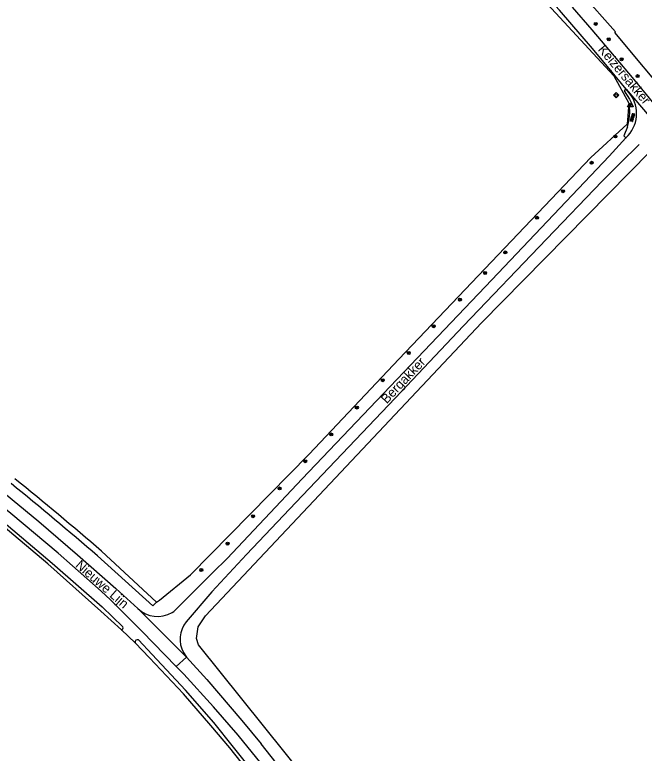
# Model space of a CAD drawing. Extents: x 124000 to 129000, y 395500 to 397503.
# Drawn here: x 126314 to 126479.9, y 396772.3 to 396968.6 of the extents above; entities that cross this region are included whole.
import ezdxf

# ---------------------------------------------------------------- set-up
doc = ezdxf.new("R2010")
doc.units = 0
for name, color, linetype in [('gg-afsc-erfafscheiding', 7, 'Continuous'), ('gg-anno-openbare ruimte label', 7, 'Continuous'), ('gg-knt-bronhoudergrens', 7, 'Continuous'), ('gg-knt-verharding', 7, 'Continuous'), ('gg-kntw-bovenkant insteek waterloop', 7, 'Continuous'), ('gt-grn-groengrens', 7, 'Continuous'), ('gt-grn-vlakafsluiter', 7, 'Continuous'), ('gt-grn-weggrens', 7, 'Continuous'), ('gt-symb-boom', 7, 'Continuous'), ('gt-symb-overige verharding', 7, 'Continuous'), ('gt-symb-rioolschacht', 7, 'Continuous'), ('gt-symb-waterafsluiter', 7, 'Continuous'), ('gx-grn-maaiveld', 7, 'Continuous')]:
    doc.layers.add(name, color=color, linetype=linetype)

# ---------------------------------------------------------------- blocks, each defined once
blk = doc.blocks.new('gt0-BOOM')
at = {"layer": 'gt-symb-boom'}
for radius in [0.4, 0.2]:
    blk.add_circle((0, 0), radius, dxfattribs=at)
blk = doc.blocks.new('gt0-OVH')
at = {"layer": 'gt-symb-overige verharding'}
for points in [[(-0.97, 0.3), (-0.97, 0.31), (-0.96, 0.32), (-0.97, 0.33), (-0.97, 0.34), (-0.98, 0.35), (-0.99, 0.35), (-1, 0.36), (-1.01, 0.35), (-1.02, 0.35), (-1.03, 0.34), (-1.03, 0.33), (-1.04, 0.32), (-1.03, 0.31), (-1.03, 0.3), (-1.02, 0.29), (-1.01, 0.29), (-1, 0.28), (-0.99, 0.29), (-0.98, 0.29)], [(-0.87, 0.11), (-0.87, 0.12), (-0.86, 0.13), (-0.87, 0.14), (-0.87, 0.15), (-0.88, 0.16), (-0.89, 0.16), (-0.9, 0.16), (-0.91, 0.16), (-0.92, 0.16), (-0.93, 0.15), (-0.93, 0.14), (-0.94, 0.13), (-0.93, 0.12), (-0.93, 0.11), (-0.92, 0.1), (-0.91, 0.09), (-0.9, 0.09), (-0.89, 0.09), (-0.88, 0.1)], [(-0.77, 0.3), (-0.77, 0.31), (-0.76, 0.32), (-0.77, 0.33), (-0.77, 0.34), (-0.78, 0.35), (-0.79, 0.35), (-0.8, 0.36), (-0.81, 0.35), (-0.82, 0.35), (-0.83, 0.34), (-0.83, 0.33), (-0.84, 0.32), (-0.83, 0.31), (-0.83, 0.3), (-0.82, 0.29), (-0.81, 0.29), (-0.8, 0.28), (-0.79, 0.29), (-0.78, 0.29)], [(-0.67, 0.11), (-0.67, 0.12), (-0.66, 0.13), (-0.67, 0.14), (-0.67, 0.15), (-0.68, 0.16), (-0.69, 0.16), (-0.7, 0.16), (-0.71, 0.16), (-0.72, 0.16), (-0.73, 0.15), (-0.73, 0.14), (-0.74, 0.13), (-0.73, 0.12), (-0.73, 0.11), (-0.72, 0.1), (-0.71, 0.09), (-0.7, 0.09), (-0.69, 0.09), (-0.68, 0.1)], [(-0.57, 0.3), (-0.57, 0.31), (-0.56, 0.32), (-0.57, 0.33), (-0.57, 0.34), (-0.58, 0.35), (-0.59, 0.35), (-0.6, 0.36), (-0.61, 0.35), (-0.62, 0.35), (-0.63, 0.34), (-0.63, 0.33), (-0.64, 0.32), (-0.63, 0.31), (-0.63, 0.3), (-0.62, 0.29), (-0.61, 0.29), (-0.6, 0.28), (-0.59, 0.29), (-0.58, 0.29)], [(-0.47, 0.11), (-0.47, 0.12), (-0.46, 0.13), (-0.47, 0.14), (-0.47, 0.15), (-0.48, 0.16), (-0.49, 0.16), (-0.5, 0.16), (-0.51, 0.16), (-0.52, 0.16), (-0.53, 0.15), (-0.53, 0.14), (-0.54, 0.13), (-0.53, 0.12), (-0.53, 0.11), (-0.52, 0.1), (-0.51, 0.09), (-0.5, 0.09), (-0.49, 0.09), (-0.48, 0.1)], [(-0.37, 0.3), (-0.37, 0.31), (-0.36, 0.32), (-0.37, 0.33), (-0.37, 0.34), (-0.38, 0.35), (-0.39, 0.35), (-0.4, 0.36), (-0.41, 0.35), (-0.42, 0.35), (-0.43, 0.34), (-0.43, 0.33), (-0.44, 0.32), (-0.43, 0.31), (-0.43, 0.3), (-0.42, 0.29), (-0.41, 0.29), (-0.4, 0.28), (-0.39, 0.29), (-0.38, 0.29)], [(-0.27, 0.11), (-0.27, 0.12), (-0.26, 0.13), (-0.27, 0.14), (-0.27, 0.15), (-0.28, 0.16), (-0.29, 0.16), (-0.3, 0.16), (-0.31, 0.16), (-0.32, 0.16), (-0.33, 0.15), (-0.33, 0.14), (-0.34, 0.13), (-0.33, 0.12), (-0.33, 0.11), (-0.32, 0.1), (-0.31, 0.09), (-0.3, 0.09), (-0.29, 0.09), (-0.28, 0.1)], [(-0.17, 0.3), (-0.17, 0.31), (-0.16, 0.32), (-0.17, 0.33), (-0.17, 0.34), (-0.18, 0.35), (-0.19, 0.35), (-0.2, 0.36), (-0.21, 0.35), (-0.22, 0.35), (-0.23, 0.34), (-0.23, 0.33), (-0.24, 0.32), (-0.23, 0.31), (-0.23, 0.3), (-0.22, 0.29), (-0.21, 0.29), (-0.2, 0.28), (-0.19, 0.29), (-0.18, 0.29)], [(-0.07, 0.11), (-0.07, 0.12), (-0.06, 0.13), (-0.07, 0.14), (-0.07, 0.15), (-0.08, 0.16), (-0.09, 0.16), (-0.1, 0.16), (-0.11, 0.16), (-0.12, 0.16), (-0.13, 0.15), (-0.13, 0.14), (-0.14, 0.13), (-0.13, 0.12), (-0.13, 0.11), (-0.12, 0.1), (-0.11, 0.09), (-0.1, 0.09), (-0.09, 0.09), (-0.08, 0.1)], [(0.03, 0.3), (0.03, 0.31), (0.04, 0.32), (0.03, 0.33), (0.03, 0.34), (0.02, 0.35), (0.01, 0.35), (0, 0.36), (-0.01, 0.35), (-0.02, 0.35), (-0.03, 0.34), (-0.03, 0.33), (-0.04, 0.32), (-0.03, 0.31), (-0.03, 0.3), (-0.02, 0.29), (-0.01, 0.29), (0, 0.28), (0.01, 0.29), (0.02, 0.29)], [(0.13, 0.11), (0.13, 0.12), (0.14, 0.13), (0.13, 0.14), (0.13, 0.15), (0.12, 0.16), (0.11, 0.16), (0.1, 0.16), (0.09, 0.16), (0.08, 0.16), (0.07, 0.15), (0.07, 0.14), (0.06, 0.13), (0.07, 0.12), (0.07, 0.11), (0.08, 0.1), (0.09, 0.09), (0.1, 0.09), (0.11, 0.09), (0.12, 0.1)], [(0.23, 0.3), (0.23, 0.31), (0.24, 0.32), (0.23, 0.33), (0.23, 0.34), (0.22, 0.35), (0.21, 0.35), (0.2, 0.36), (0.19, 0.35), (0.18, 0.35), (0.17, 0.34), (0.17, 0.33), (0.16, 0.32), (0.17, 0.31), (0.17, 0.3), (0.18, 0.29), (0.19, 0.29), (0.2, 0.28), (0.21, 0.29), (0.22, 0.29)], [(0.33, 0.11), (0.33, 0.12), (0.34, 0.13), (0.33, 0.14), (0.33, 0.15), (0.32, 0.16), (0.31, 0.16), (0.3, 0.16), (0.29, 0.16), (0.28, 0.16), (0.27, 0.15), (0.27, 0.14), (0.26, 0.13), (0.27, 0.12), (0.27, 0.11), (0.28, 0.1), (0.29, 0.09), (0.3, 0.09), (0.31, 0.09), (0.32, 0.1)], [(0.43, 0.3), (0.43, 0.31), (0.44, 0.32), (0.43, 0.33), (0.43, 0.34), (0.42, 0.35), (0.41, 0.35), (0.4, 0.36), (0.39, 0.35), (0.38, 0.35), (0.37, 0.34), (0.37, 0.33), (0.36, 0.32), (0.37, 0.31), (0.37, 0.3), (0.38, 0.29), (0.39, 0.29), (0.4, 0.28), (0.41, 0.29), (0.42, 0.29)], [(0.53, 0.11), (0.53, 0.12), (0.54, 0.13), (0.53, 0.14), (0.53, 0.15), (0.52, 0.16), (0.51, 0.16), (0.5, 0.16), (0.49, 0.16), (0.48, 0.16), (0.47, 0.15), (0.47, 0.14), (0.46, 0.13), (0.47, 0.12), (0.47, 0.11), (0.48, 0.1), (0.49, 0.09), (0.5, 0.09), (0.51, 0.09), (0.52, 0.1)], [(0.63, 0.3), (0.63, 0.31), (0.64, 0.32), (0.63, 0.33), (0.63, 0.34), (0.62, 0.35), (0.61, 0.35), (0.6, 0.36), (0.59, 0.35), (0.58, 0.35), (0.57, 0.34), (0.57, 0.33), (0.56, 0.32), (0.57, 0.31), (0.57, 0.3), (0.58, 0.29), (0.59, 0.29), (0.6, 0.28), (0.61, 0.29), (0.62, 0.29)], [(0.73, 0.11), (0.73, 0.12), (0.74, 0.13), (0.73, 0.14), (0.73, 0.15), (0.72, 0.16), (0.71, 0.16), (0.7, 0.16), (0.69, 0.16), (0.68, 0.16), (0.67, 0.15), (0.67, 0.14), (0.66, 0.13), (0.67, 0.12), (0.67, 0.11), (0.68, 0.1), (0.69, 0.09), (0.7, 0.09), (0.71, 0.09), (0.72, 0.1)], [(0.83, 0.3), (0.83, 0.31), (0.84, 0.32), (0.83, 0.33), (0.83, 0.34), (0.82, 0.35), (0.81, 0.35), (0.8, 0.36), (0.79, 0.35), (0.78, 0.35), (0.77, 0.34), (0.77, 0.33), (0.76, 0.32), (0.77, 0.31), (0.77, 0.3), (0.78, 0.29), (0.79, 0.29), (0.8, 0.28), (0.81, 0.29), (0.82, 0.29)], [(0.93, 0.11), (0.93, 0.12), (0.94, 0.13), (0.93, 0.14), (0.93, 0.15), (0.92, 0.16), (0.91, 0.16), (0.9, 0.16), (0.89, 0.16), (0.88, 0.16), (0.87, 0.15), (0.87, 0.14), (0.86, 0.13), (0.87, 0.12), (0.87, 0.11), (0.88, 0.1), (0.89, 0.09), (0.9, 0.09), (0.91, 0.09), (0.92, 0.1)], [(1.03, 0.3), (1.03, 0.31), (1.04, 0.32), (1.03, 0.33), (1.03, 0.34), (1.02, 0.35), (1.01, 0.35), (1, 0.36), (0.99, 0.35), (0.98, 0.35), (0.97, 0.34), (0.97, 0.33), (0.96, 0.32), (0.97, 0.31), (0.97, 0.3), (0.98, 0.29), (0.99, 0.29), (1, 0.28), (1.01, 0.29), (1.02, 0.29)], [(-0.97, -0.14), (-0.97, -0.13), (-0.96, -0.12), (-0.97, -0.11), (-0.97, -0.1), (-0.98, -0.09), (-0.99, -0.09), (-1, -0.08), (-1.01, -0.09), (-1.02, -0.09), (-1.03, -0.1), (-1.03, -0.11), (-1.04, -0.12), (-1.03, -0.13), (-1.03, -0.14), (-1.02, -0.15), (-1.01, -0.15), (-1, -0.16), (-0.99, -0.15), (-0.98, -0.15)], [(-0.87, -0.33), (-0.87, -0.32), (-0.86, -0.31), (-0.87, -0.3), (-0.87, -0.29), (-0.88, -0.28), (-0.89, -0.28), (-0.9, -0.28), (-0.91, -0.28), (-0.92, -0.28), (-0.93, -0.29), (-0.93, -0.3), (-0.94, -0.31), (-0.93, -0.32), (-0.93, -0.33), (-0.92, -0.34), (-0.91, -0.35), (-0.9, -0.35), (-0.89, -0.35), (-0.88, -0.34)], [(-0.77, -0.14), (-0.77, -0.13), (-0.76, -0.12), (-0.77, -0.11), (-0.77, -0.1), (-0.78, -0.09), (-0.79, -0.09), (-0.8, -0.08), (-0.81, -0.09), (-0.82, -0.09), (-0.83, -0.1), (-0.83, -0.11), (-0.84, -0.12), (-0.83, -0.13), (-0.83, -0.14), (-0.82, -0.15), (-0.81, -0.15), (-0.8, -0.16), (-0.79, -0.15), (-0.78, -0.15)], [(-0.67, -0.33), (-0.67, -0.32), (-0.66, -0.31), (-0.67, -0.3), (-0.67, -0.29), (-0.68, -0.28), (-0.69, -0.28), (-0.7, -0.28), (-0.71, -0.28), (-0.72, -0.28), (-0.73, -0.29), (-0.73, -0.3), (-0.74, -0.31), (-0.73, -0.32), (-0.73, -0.33), (-0.72, -0.34), (-0.71, -0.35), (-0.7, -0.35), (-0.69, -0.35), (-0.68, -0.34)], [(-0.57, -0.14), (-0.57, -0.13), (-0.56, -0.12), (-0.57, -0.11), (-0.57, -0.1), (-0.58, -0.09), (-0.59, -0.09), (-0.6, -0.08), (-0.61, -0.09), (-0.62, -0.09), (-0.63, -0.1), (-0.63, -0.11), (-0.64, -0.12), (-0.63, -0.13), (-0.63, -0.14), (-0.62, -0.15), (-0.61, -0.15), (-0.6, -0.16), (-0.59, -0.15), (-0.58, -0.15)], [(-0.47, -0.33), (-0.47, -0.32), (-0.46, -0.31), (-0.47, -0.3), (-0.47, -0.29), (-0.48, -0.28), (-0.49, -0.28), (-0.5, -0.28), (-0.51, -0.28), (-0.52, -0.28), (-0.53, -0.29), (-0.53, -0.3), (-0.54, -0.31), (-0.53, -0.32), (-0.53, -0.33), (-0.52, -0.34), (-0.51, -0.35), (-0.5, -0.35), (-0.49, -0.35), (-0.48, -0.34)], [(-0.37, -0.14), (-0.37, -0.13), (-0.36, -0.12), (-0.37, -0.11), (-0.37, -0.1), (-0.38, -0.09), (-0.39, -0.09), (-0.4, -0.08), (-0.41, -0.09), (-0.42, -0.09), (-0.43, -0.1), (-0.43, -0.11), (-0.44, -0.12), (-0.43, -0.13), (-0.43, -0.14), (-0.42, -0.15), (-0.41, -0.15), (-0.4, -0.16), (-0.39, -0.15), (-0.38, -0.15)], [(-0.27, -0.33), (-0.27, -0.32), (-0.26, -0.31), (-0.27, -0.3), (-0.27, -0.29), (-0.28, -0.28), (-0.29, -0.28), (-0.3, -0.28), (-0.31, -0.28), (-0.32, -0.28), (-0.33, -0.29), (-0.33, -0.3), (-0.34, -0.31), (-0.33, -0.32), (-0.33, -0.33), (-0.32, -0.34), (-0.31, -0.35), (-0.3, -0.35), (-0.29, -0.35), (-0.28, -0.34)], [(-0.17, -0.14), (-0.17, -0.13), (-0.16, -0.12), (-0.17, -0.11), (-0.17, -0.1), (-0.18, -0.09), (-0.19, -0.09), (-0.2, -0.08), (-0.21, -0.09), (-0.22, -0.09), (-0.23, -0.1), (-0.23, -0.11), (-0.24, -0.12), (-0.23, -0.13), (-0.23, -0.14), (-0.22, -0.15), (-0.21, -0.15), (-0.2, -0.16), (-0.19, -0.15), (-0.18, -0.15)], [(-0.07, -0.33), (-0.07, -0.32), (-0.06, -0.31), (-0.07, -0.3), (-0.07, -0.29), (-0.08, -0.28), (-0.09, -0.28), (-0.1, -0.28), (-0.11, -0.28), (-0.12, -0.28), (-0.13, -0.29), (-0.13, -0.3), (-0.14, -0.31), (-0.13, -0.32), (-0.13, -0.33), (-0.12, -0.34), (-0.11, -0.35), (-0.1, -0.35), (-0.09, -0.35), (-0.08, -0.34)], [(0.03, -0.14), (0.03, -0.13), (0.04, -0.12), (0.03, -0.11), (0.03, -0.1), (0.02, -0.09), (0.01, -0.09), (0, -0.08), (-0.01, -0.09), (-0.02, -0.09), (-0.03, -0.1), (-0.03, -0.11), (-0.04, -0.12), (-0.03, -0.13), (-0.03, -0.14), (-0.02, -0.15), (-0.01, -0.15), (0, -0.16), (0.01, -0.15), (0.02, -0.15)], [(0.13, -0.33), (0.13, -0.32), (0.14, -0.31), (0.13, -0.3), (0.13, -0.29), (0.12, -0.28), (0.11, -0.28), (0.1, -0.28), (0.09, -0.28), (0.08, -0.28), (0.07, -0.29), (0.07, -0.3), (0.06, -0.31), (0.07, -0.32), (0.07, -0.33), (0.08, -0.34), (0.09, -0.35), (0.1, -0.35), (0.11, -0.35), (0.12, -0.34)], [(0.23, -0.14), (0.23, -0.13), (0.24, -0.12), (0.23, -0.11), (0.23, -0.1), (0.22, -0.09), (0.21, -0.09), (0.2, -0.08), (0.19, -0.09), (0.18, -0.09), (0.17, -0.1), (0.17, -0.11), (0.16, -0.12), (0.17, -0.13), (0.17, -0.14), (0.18, -0.15), (0.19, -0.15), (0.2, -0.16), (0.21, -0.15), (0.22, -0.15)], [(0.33, -0.33), (0.33, -0.32), (0.34, -0.31), (0.33, -0.3), (0.33, -0.29), (0.32, -0.28), (0.31, -0.28), (0.3, -0.28), (0.29, -0.28), (0.28, -0.28), (0.27, -0.29), (0.27, -0.3), (0.26, -0.31), (0.27, -0.32), (0.27, -0.33), (0.28, -0.34), (0.29, -0.35), (0.3, -0.35), (0.31, -0.35), (0.32, -0.34)], [(0.43, -0.14), (0.43, -0.13), (0.44, -0.12), (0.43, -0.11), (0.43, -0.1), (0.42, -0.09), (0.41, -0.09), (0.4, -0.08), (0.39, -0.09), (0.38, -0.09), (0.37, -0.1), (0.37, -0.11), (0.36, -0.12), (0.37, -0.13), (0.37, -0.14), (0.38, -0.15), (0.39, -0.15), (0.4, -0.16), (0.41, -0.15), (0.42, -0.15)], [(0.53, -0.33), (0.53, -0.32), (0.54, -0.31), (0.53, -0.3), (0.53, -0.29), (0.52, -0.28), (0.51, -0.28), (0.5, -0.28), (0.49, -0.28), (0.48, -0.28), (0.47, -0.29), (0.47, -0.3), (0.46, -0.31), (0.47, -0.32), (0.47, -0.33), (0.48, -0.34), (0.49, -0.35), (0.5, -0.35), (0.51, -0.35), (0.52, -0.34)], [(0.63, -0.14), (0.63, -0.13), (0.64, -0.12), (0.63, -0.11), (0.63, -0.1), (0.62, -0.09), (0.61, -0.09), (0.6, -0.08), (0.59, -0.09), (0.58, -0.09), (0.57, -0.1), (0.57, -0.11), (0.56, -0.12), (0.57, -0.13), (0.57, -0.14), (0.58, -0.15), (0.59, -0.15), (0.6, -0.16), (0.61, -0.15), (0.62, -0.15)], [(0.73, -0.33), (0.73, -0.32), (0.74, -0.31), (0.73, -0.3), (0.73, -0.29), (0.72, -0.28), (0.71, -0.28), (0.7, -0.28), (0.69, -0.28), (0.68, -0.28), (0.67, -0.29), (0.67, -0.3), (0.66, -0.31), (0.67, -0.32), (0.67, -0.33), (0.68, -0.34), (0.69, -0.35), (0.7, -0.35), (0.71, -0.35), (0.72, -0.34)], [(0.83, -0.14), (0.83, -0.13), (0.84, -0.12), (0.83, -0.11), (0.83, -0.1), (0.82, -0.09), (0.81, -0.09), (0.8, -0.08), (0.79, -0.09), (0.78, -0.09), (0.77, -0.1), (0.77, -0.11), (0.76, -0.12), (0.77, -0.13), (0.77, -0.14), (0.78, -0.15), (0.79, -0.15), (0.8, -0.16), (0.81, -0.15), (0.82, -0.15)], [(0.93, -0.33), (0.93, -0.32), (0.94, -0.31), (0.93, -0.3), (0.93, -0.29), (0.92, -0.28), (0.91, -0.28), (0.9, -0.28), (0.89, -0.28), (0.88, -0.28), (0.87, -0.29), (0.87, -0.3), (0.86, -0.31), (0.87, -0.32), (0.87, -0.33), (0.88, -0.34), (0.89, -0.35), (0.9, -0.35), (0.91, -0.35), (0.92, -0.34)], [(1.03, -0.14), (1.03, -0.13), (1.04, -0.12), (1.03, -0.11), (1.03, -0.1), (1.02, -0.09), (1.01, -0.09), (1, -0.08), (0.99, -0.09), (0.98, -0.09), (0.97, -0.1), (0.97, -0.11), (0.96, -0.12), (0.97, -0.13), (0.97, -0.14), (0.98, -0.15), (0.99, -0.15), (1, -0.16), (1.01, -0.15), (1.02, -0.15)]]:
    blk.add_lwpolyline(points, close=True, dxfattribs=at)
blk = doc.blocks.new('gt0-WAFSL')
at = {"layer": 'gt-symb-waterafsluiter'}
for p, q in [((-0.5, -0.33), (0, 0.67)), ((0, 0.67), (0.5, -0.33)), ((0.5, -0.33), (-0.5, -0.33))]:
    blk.add_line(p, q, dxfattribs=at)
blk = doc.blocks.new('gt0-RS')
at = {"layer": 'gt-symb-rioolschacht'}
blk.add_lwpolyline([(-0.5, -0.5), (0.5, -0.5), (0.5, 0.5), (-0.5, 0.5)], close=True, dxfattribs=at)
blk.add_circle((0, 0), 0.375, dxfattribs=at)

msp = doc.modelspace()

# ---------------------------------------------------------------- linework, layer by layer
at = {"layer": 'gg-afsc-erfafscheiding'}
for points in [[(126510.47, 396905.94), (126488.14, 396932.03), (126485.07, 396933.22), (126482.92, 396932.4), (126438.04, 396886.69)], [(126352.49, 396812.96), (126360.73, 396819.68), (126392.2, 396851.78), (126416.03, 396877.09)]]:
    msp.add_lwpolyline(points, dxfattribs=at)
at = {"layer": 'gg-knt-bronhoudergrens'}
msp.add_line((126342.32, 396805.11), (126345.95, 396801.64), dxfattribs=at)
msp.add_lwpolyline([(126473.18, 396952.37), (126446.7, 396981.11), (126398.82, 397026.17)], dxfattribs=at)
at = {"layer": 'gg-knt-verharding'}
for p, q in [((126476.49, 396948.88), (126472.35, 396953.88)), ((126477.54, 396947.56), (126476.49, 396948.88)), ((126476.42, 396935.92), (126476.44, 396935.95)), ((126358.84, 396799.02), (126359.67, 396797.83))]:
    msp.add_line(p, q, dxfattribs=at)
for points in [[(126472.35, 396953.88), (126467.53, 396959.7), (126458.73, 396969.82), (126452.09, 396977.17), (126444.82, 396984.68), (126436.8, 396992.63), (126402.35, 397025.76), (126373.84, 397053.02), (126353.38, 397072.64), (126324.99, 397100.03)], [(126485.91, 396942.48), (126478.56, 396951.43), (126473.37, 396957.63), (126467.41, 396964.61), (126462.18, 396970.67)], [(126476.49, 396948.88), (126475.94, 396948.42), (126477.38, 396946.18), (126478.05, 396944.74), (126477.28, 396944.62)], [(126476.83, 396938.86), (126475.86, 396936.43), (126476.42, 396935.92)], [(126355.79, 396809.67), (126356.25, 396809.93), (126356.84, 396810.45), (126361.61, 396815.28), (126366.67, 396820.3), (126370.43, 396824.06), (126390.39, 396845.25), (126440.74, 396898.15), (126471.92, 396931.02), (126476.42, 396935.92)], [(126479.94, 396934.1), (126474.85, 396929.21), (126470.07, 396924.38), (126455.3, 396908.99), (126433.21, 396885.87), (126415.09, 396866.7), (126388.71, 396838.97), (126375.59, 396825.08), (126366.36, 396815.2), (126359.56, 396807.19)], [(126280.27, 396864.57), (126285.85, 396860.96), (126291.2, 396857.12), (126296.46, 396853.1), (126309.7, 396842.64), (126320.43, 396833.86), (126330.68, 396825.05), (126340.87, 396816.04), (126346.69, 396810.77)], [(126356.9, 396795.33), (126347.89, 396804.66), (126339.43, 396813.03), (126336.96, 396815.36), (126325.52, 396825.43), (126312.96, 396835.99), (126299.48, 396846.83), (126291.48, 396853.01), (126286.37, 396856.78), (126279.43, 396861.42)], [(126359.67, 396797.83), (126365.06, 396791.85), (126374.35, 396781), (126379.48, 396774.76)], [(126379.5, 396769.51), (126373.33, 396777.08), (126366.85, 396784.56), (126358.9, 396793.26), (126356.9, 396795.33)], [(126414.17, 396731.07), (126403.86, 396743.66), (126402.65, 396746.8), (126389.73, 396763.21), (126387.08, 396765.08), (126379.48, 396774.76)]]:
    msp.add_lwpolyline(points, dxfattribs=at)
for centre, radius, start, end in [((126470.49, 396942.37), 8.75, 312.8624, 36.3813), ((126464.91, 396942.69), 12.52, 342.2043, 8.8796), ((126351.95, 396816.14), 7.52, 225.5852, 300.6671), ((126365.32, 396802.57), 7.39, 141.2358, 208.6801)]:
    msp.add_arc(centre, radius, start, end, dxfattribs=at)
at = {"layer": 'gg-kntw-bovenkant insteek waterloop'}
msp.add_line((126351.66, 396812.43), (126337.06, 396825.99), dxfattribs=at)
for points in [[(126225.73, 396877.83), (126226.08, 396879.33), (126227.38, 396878.93), (126242.21, 396874.18), (126254.73, 396870.07), (126261.76, 396867.21), (126271.86, 396862.49), (126281.37, 396856.54), (126290.14, 396850.4), (126300.93, 396842.06), (126309.35, 396835.14), (126323.97, 396822.8), (126337.2, 396811.2), (126342.75, 396805.84)], [(126342.32, 396805.11), (126336.9, 396810.01), (126322.81, 396822.59), (126309.12, 396834.05), (126300.64, 396840.87), (126289.61, 396849.52), (126280.85, 396855.66), (126271.34, 396861.55), (126261.52, 396866.11), (126251.58, 396869.79), (126243.37, 396872.61), (126233.92, 396875.63), (126225.73, 396877.83)], [(126335.95, 396824.74), (126350.7, 396811.43), (126351.66, 396812.43)], [(126397.67, 396739.12), (126386.43, 396754.27), (126378.53, 396764.42), (126371.17, 396773.66), (126366.13, 396779.67), (126358.86, 396788.07), (126349.79, 396797.67), (126345.95, 396801.64)], [(126398.72, 396739.76), (126393.82, 396746.11), (126386.99, 396755.11), (126379.44, 396764.62), (126372.08, 396773.86), (126366.93, 396780.39), (126359.37, 396788.99), (126350.54, 396798.55), (126346.87, 396802.45)]]:
    msp.add_lwpolyline(points, dxfattribs=at)
for centre, radius, start, end in [((125644.04, 396019.71), 1063.19, 49.31986, 50.9391), ((125699.83, 396089.8), 972, 49.12226, 50.88483), ((126342.33, 396805.59), 0.486, 267.8741, 30.5207), ((126346.69, 396801.73), 0.745, 75.6689, 186.9483)]:
    msp.add_arc(centre, radius, start, end, dxfattribs=at)
at = {"layer": 'gt-grn-groengrens'}
msp.add_line((126472.35, 396953.88), (126473.18, 396952.37), dxfattribs=at)
for points in [[(126489.12, 396945.14), (126473.42, 396963.95), (126473.64, 396964.14), (126464.5, 396974.47)], [(126473.18, 396952.37), (126477.15, 396945.09), (126476.75, 396939.53), (126467.09, 396930.67), (126416.03, 396877.09)]]:
    msp.add_lwpolyline(points, dxfattribs=at)
at = {"layer": 'gt-grn-vlakafsluiter'}
msp.add_line((126351.66, 396812.43), (126352.49, 396812.96), dxfattribs=at)
at = {"layer": 'gt-grn-weggrens'}
for p, q in [((126476.49, 396948.88), (126489.05, 396933.93)), ((126346.69, 396810.77), (126359.67, 396797.83)), ((126359.67, 396797.83), (126356.9, 396795.33))]:
    msp.add_line(p, q, dxfattribs=at)
at = {"layer": 'gx-grn-maaiveld'}
for points in [[(126362.83, 396801.07), (126362.33, 396802.75), (126362.73, 396805.83), (126364.72, 396808.8), (126438.04, 396886.69)], [(126529.63, 396622.69), (126493.34, 396656.17), (126464.56, 396683.46), (126445.39, 396701.53), (126433.26, 396714.18), (126421.44, 396727.43), (126407.13, 396744.94), (126391.62, 396765.19), (126362.83, 396801.07)]]:
    msp.add_lwpolyline(points, dxfattribs=at)

# ---------------------------------------------------------------- block references
at = {"layer": 'gt-symb-boom'}
for p in [(126468.4, 396966.2), (126471.85, 396962.11), (126475.25, 396956.79), (126479.51, 396952.33), (126473.61, 396936.28), (126467.29, 396929.28), (126459.71, 396921.7), (126452.82, 396914.65), (126444.36, 396905.43), (126439, 396899.97), (126432.3, 396892.87), (126425.33, 396885.82), (126418.7, 396878.69), (126411.8, 396871.45), (126404.9, 396864.18), (126398.1, 396857.02), (126391.19, 396849.92), (126384.37, 396842.66), (126377.33, 396835.28), (126370.54, 396828), (126363.56, 396820.97)]:
    msp.add_blockref('gt0-BOOM', p, dxfattribs=at)
at = {"layer": 'gt-symb-overige verharding', "rotation": -106.73216022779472}
msp.add_blockref('gt0-OVH', (126478.15, 396941.33), dxfattribs=at)
at = {"layer": 'gt-symb-rioolschacht', "rotation": 44.918959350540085}
msp.add_blockref('gt0-RS', (126473.83, 396947.23), dxfattribs=at)
at = {"layer": 'gt-symb-waterafsluiter'}
for p in [(126477.37, 396944.51), (126477.86, 396944.44)]:
    msp.add_blockref('gt0-WAFSL', p, dxfattribs=at)

# ---------------------------------------------------------------- texts
at = {"layer": 'gg-anno-openbare ruimte label'}
for s, rotation, p in [('Keizersakker', 310.1, (126468.82, 396959.31)), ('Bergakker', 46.5, (126412.85, 396865.04)), ('Nieuwe Lijn', 318.8, (126329.91, 396821.96))]:
    msp.add_text(s, height=2.5, rotation=rotation, dxfattribs=at).set_placement(p)

doc.saveas('drawing.dxf')
